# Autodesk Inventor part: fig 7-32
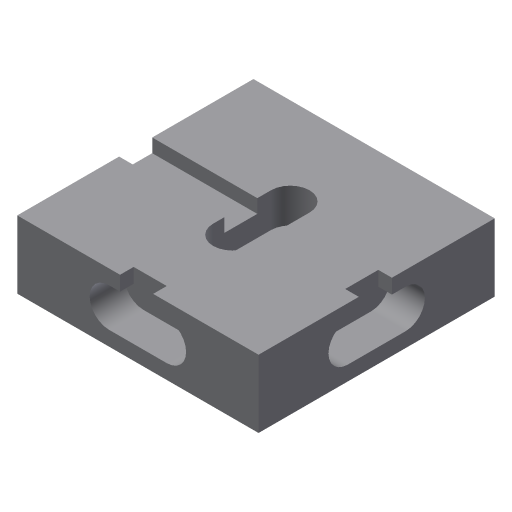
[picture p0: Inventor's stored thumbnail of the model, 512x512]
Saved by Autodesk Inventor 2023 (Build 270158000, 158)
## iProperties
Created: 2004-05
Part Number: fig 7-32
Document SubType Name: Modeling
Designer: CADCIM Technologies
Manufacturer: Standard
Standards Organization: Custom
Density: 1 g/cm^3
Material: Generic
Appearance: Default
Author: CADCIM Technologies
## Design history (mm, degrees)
sketch "Sketch1"
  geometry: L1 (-30.233, -25.517)-(22.302, -25.517); L2 (22.302, -25.517)-(22.302, 25.904); L3 (22.302, 25.904)-(-30.233, 25.904); L4 (-30.233, 25.904)-(-30.233, -25.517)
  constraints: 8 end point, 2 parallel, 1 horizontal, 1 perpendicular
extrude "Extrusion1" new body sketch "Sketch1" distance "d0" = 14.75; taper "d1" = 0 deg
sketch "Sketch2"
  geometry: L1 (1.047, -5.75)-(1.047, 6.846); L2 (-7.35, 6.845)-(-7.35, -5.75); A1 r 4.198 centre (-3.152, 6.846) between (1.047, 6.846) and (-7.35, 6.845); A2 r 4.198 centre (-3.152, -5.75) between (-7.35, -5.75) and (1.047, -5.75)
  constraints: 4 end point, 4 point on circle, 4 tangent, 2 centre point, 1 parallel
extrude "Extrusion2" cut sketch "Sketch2" distance "d2" = 7.5; taper "d3" = 0 deg
sketch "Sketch3"
  geometry: L1 (-7.5, 0)-(-7.5, 12.595) reference; L2 (-7.5, 0)-(0, 0) reference; L3 (-7.5, 2.416)-(-4.537, 2.416); L4 (-4.537, 2.416)-(-4.537, 9.616); L5 (-4.537, 9.616)-(-7.5, 9.616)
  constraints: 6 end point, 2 perpendicular, 2 point on line, 1 parallel
extrude "Extrusion3" cut sketch "Sketch3" extent not by distance; stored distance "d4" = 6.75; taper "d5" = 0 deg
sketch "Sketch4"
  geometry: L1 (1.047, -5.75)-(1.047, 6.846); L2 (-7.35, 6.845)-(-7.35, -5.75); A1 r 4.198 centre (-3.152, 6.846) between (1.047, 6.846) and (-7.35, 6.845); A2 r 4.198 centre (-3.152, -5.75) between (-7.35, -5.75) and (1.047, -5.75)
  constraints: 4 end point, 4 point on circle, 4 tangent, 2 centre point, 1 parallel
extrude "Extrusion4" cut sketch "Sketch4" taper "d7" = 0 deg; distance "d8" = 7.5
sketch "Sketch5"
  geometry: L1 (-7.5, 0)-(-7.5, 12.595) reference; L2 (-7.5, 0)-(0, 0) reference; L3 (-7.5, 2.416)-(-4.537, 2.416); L4 (-4.537, 2.416)-(-4.537, 9.616); L5 (-4.537, 9.616)-(-7.5, 9.616)
  constraints: 6 end point, 2 perpendicular, 2 point on line, 1 parallel
extrude "Extrusion5" cut sketch "Sketch5" extent not by distance; taper "d10" = 0 deg; stored distance "d11" = 6.75
sketch "Sketch6"
  geometry: L1 (1.047, -5.75)-(1.047, 6.846); L2 (-7.35, 6.845)-(-7.35, -5.75); A1 r 4.198 centre (-3.152, 6.846) between (1.047, 6.846) and (-7.35, 6.845); A2 r 4.198 centre (-3.152, -5.75) between (-7.35, -5.75) and (1.047, -5.75)
  constraints: 4 end point, 4 point on circle, 4 tangent, 2 centre point, 1 parallel
extrude "Extrusion6" cut sketch "Sketch6" taper "d13" = 0 deg; distance "d14" = 7.5
sketch "Sketch7"
  geometry: L1 (-7.5, 0)-(-7.5, 12.595) reference; L2 (-7.5, 0)-(0, 0) reference; L3 (-7.5, 2.416)-(-4.537, 2.416); L4 (-4.537, 2.416)-(-4.537, 9.616); L5 (-4.537, 9.616)-(-7.5, 9.616)
  constraints: 6 end point, 2 perpendicular, 2 point on line, 1 parallel
extrude "Extrusion7" cut sketch "Sketch7" extent not by distance; taper "d16" = 0 deg; stored distance "d17" = 6.75
body "Solid1"
